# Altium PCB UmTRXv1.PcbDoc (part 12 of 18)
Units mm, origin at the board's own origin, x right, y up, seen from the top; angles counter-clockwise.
Board outline 172 x 113 mm, 6 copper layers (Top Layer, GND, MidLayer1, Mid-Layer 2, InternalPlane2, Bottom Layer); 766 components, 613 nets, 3008 pads, 1360 vias.
Unrouted connection lines stored in the file: 2.
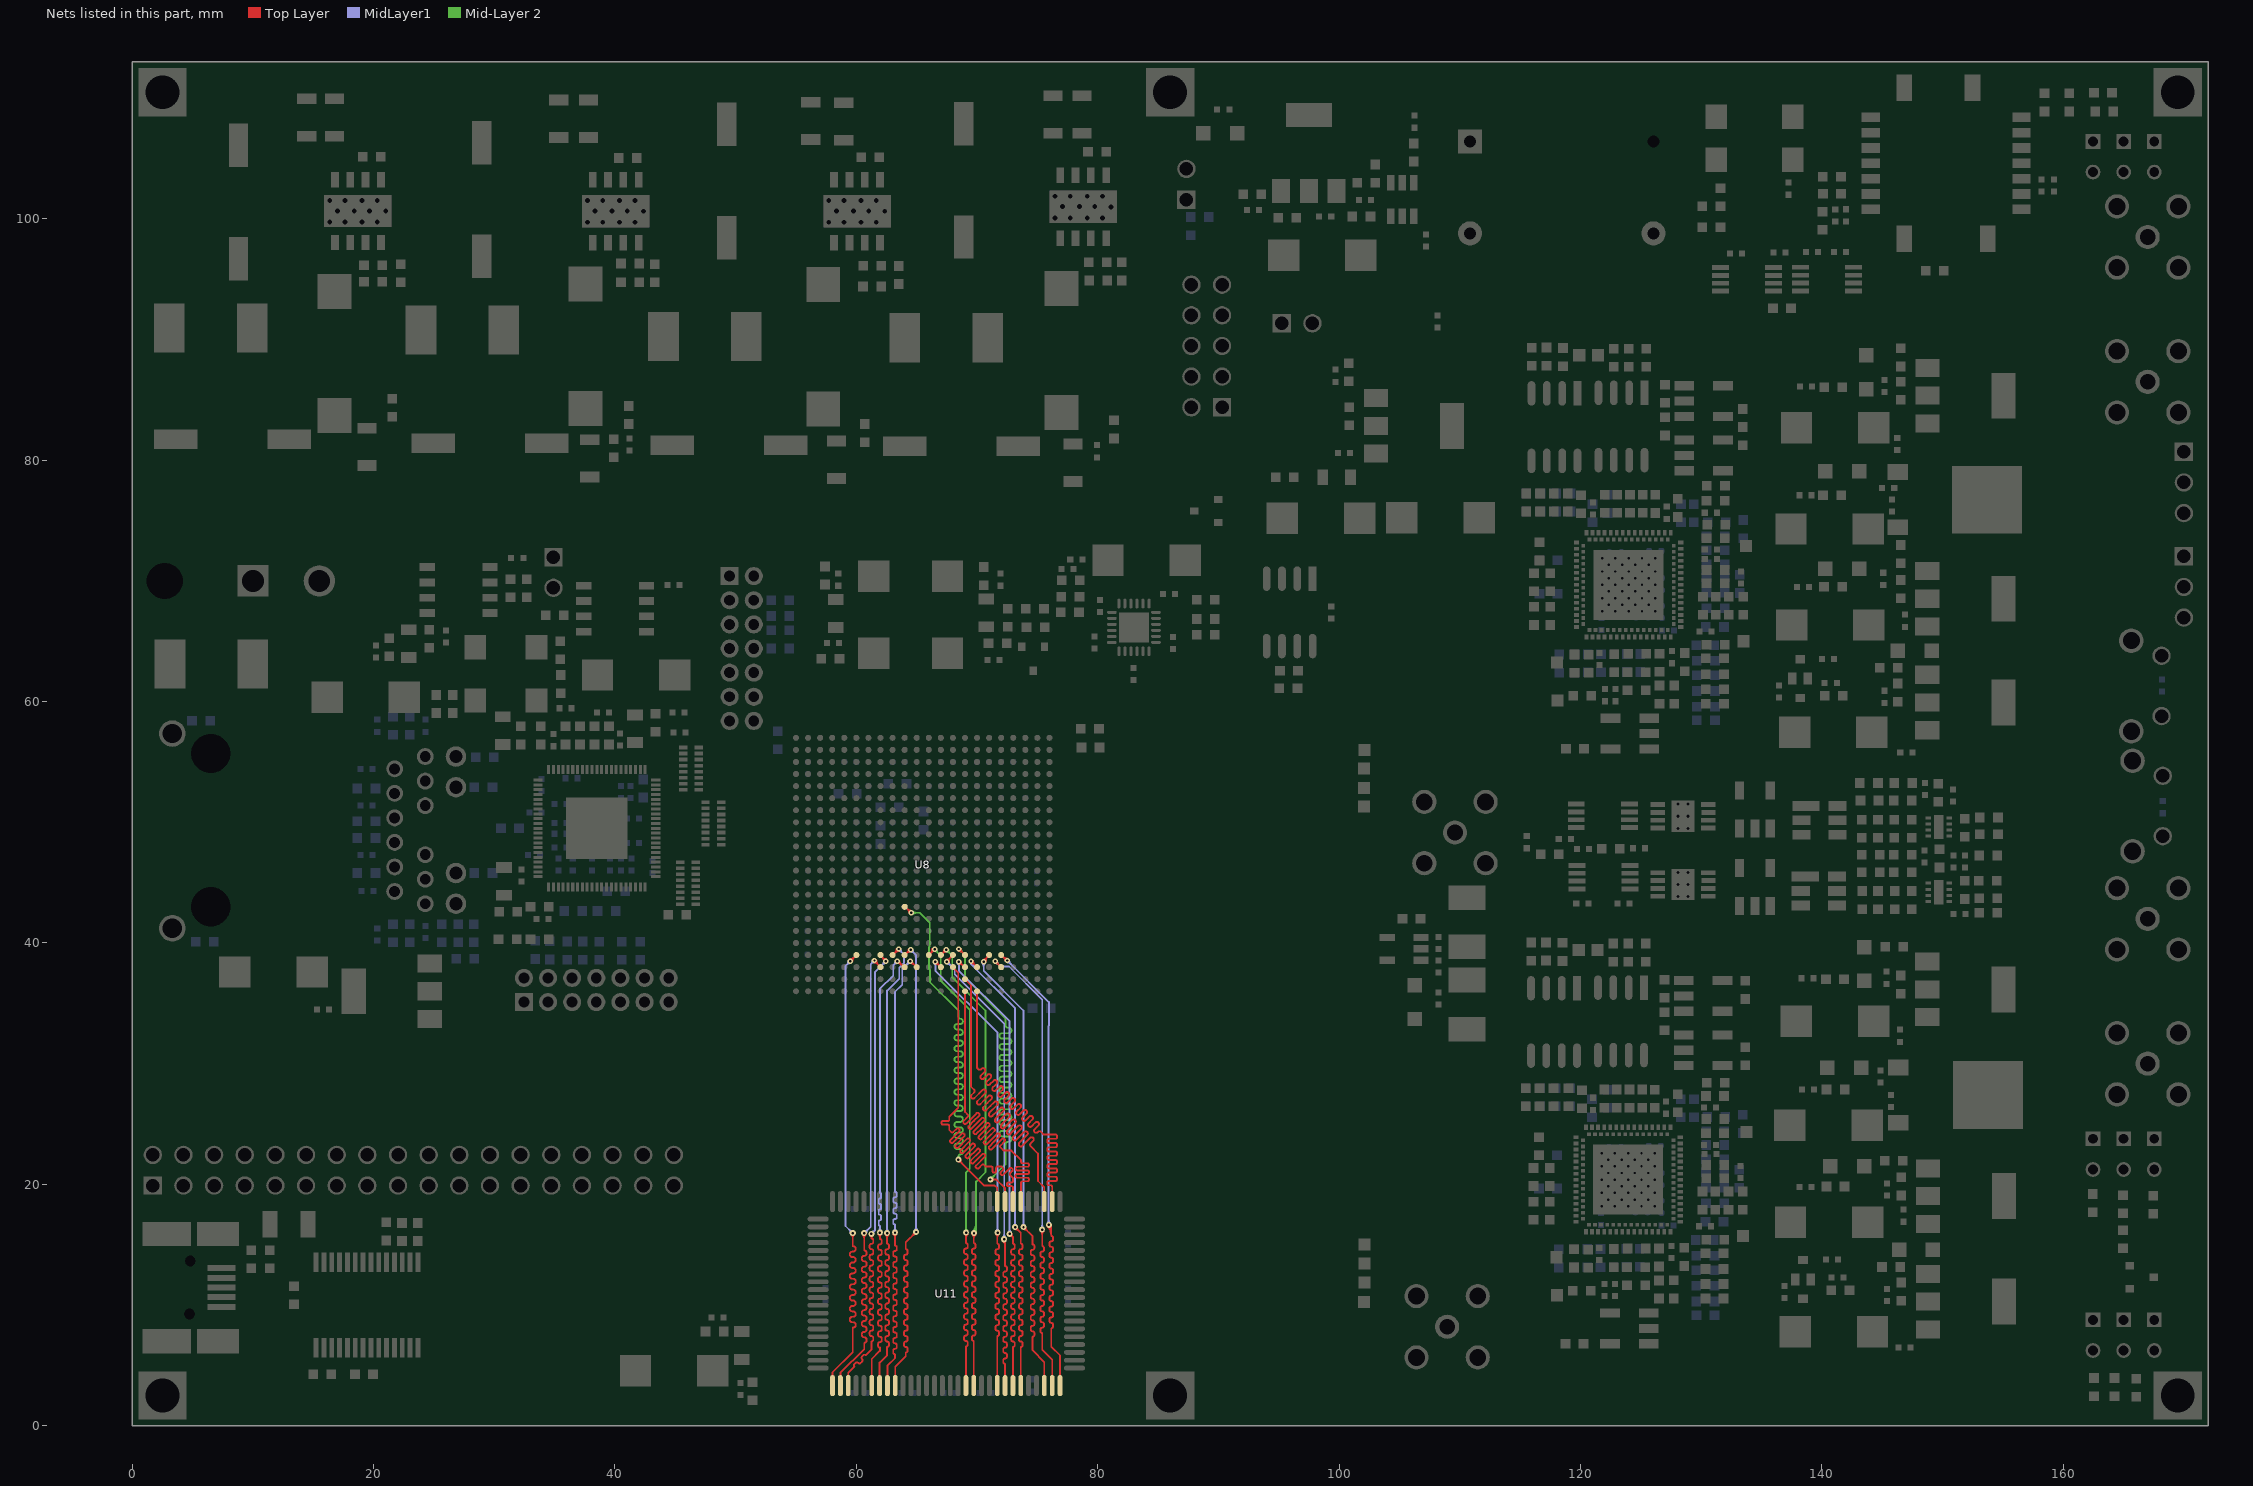
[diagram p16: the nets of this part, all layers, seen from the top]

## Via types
v1: diameter 0.45, hole 0.2, Top Layer to Bottom Layer, tented both sides, 554 vias
v2: diameter 0.5, hole 0.2, Top Layer to Bottom Layer, tented both sides, 468 vias
v3: diameter 0.7, hole 0.3, Top Layer to Bottom Layer, tented both sides, 206 vias
v4: diameter 0.4, hole 0.2, Top Layer to Bottom Layer, tented both sides, 82 vias
v5: diameter 0.8, hole 0.3, Top Layer to Bottom Layer, tented both sides, 16 vias
v6: diameter 0.6, hole 0.25, Top Layer to Bottom Layer, tented both sides, 16 vias
v7: diameter 0.5, hole 0.3, Top Layer to Bottom Layer, tented both sides, 8 vias
v8: diameter 0.7, hole 0.3, Top Layer to Bottom Layer, 4 vias
v9: diameter 0.6, hole 0.3, Top Layer to Bottom Layer, tented both sides, 4 vias
v10: diameter 0.5, hole 0.2, Top Layer to Bottom Layer, 2 vias

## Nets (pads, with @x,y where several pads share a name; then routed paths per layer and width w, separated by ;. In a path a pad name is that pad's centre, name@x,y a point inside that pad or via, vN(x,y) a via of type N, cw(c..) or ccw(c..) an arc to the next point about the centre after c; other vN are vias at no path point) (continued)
RAM_D02: U8.D13 U11.59 | length 43.8
  Top Layer w0.15: U11.59@63.225,3.325 63.225,4.875 64.1,5.75 64.1,6.075 ccw(c64.1,6.225) 64.25,6.225 64.25,6.375 ccw(c64.1,6.375) 64.1,6.525 cw(c64.1,6.675) 63.95,6.675 63.95,6.825 cw(c64.1,6.825) 64.1,6.975 ccw(c64.1,7.125) 64.25,7.125 64.25,7.275 ccw(c64.1,7.275) 64.1,7.425 cw(c64.1,7.575) 63.95,7.575 63.95,7.725 cw(c64.1,7.725) 64.1,7.875 ccw(c64.1,8.025) 64.25,8.025 64.25,8.175 ccw(c64.1,8.175) 64.1,8.325 cw(c64.1,8.475) 63.95,8.475 63.95,8.625 cw(c64.1,8.625) 64.1,8.775 ccw(c64.1,8.925) 64.25,8.925 64.25,9.075 ccw(c64.1,9.075) 64.1,9.225 cw(c64.1,9.375) 63.95,9.375 63.95,9.525 cw(c64.1,9.525) 64.1,9.675 ccw(c64.1,9.825) 64.25,9.825 64.25,9.975 ccw(c64.1,9.975) 64.1,10.125 cw(c64.1,10.275) 63.95,10.275 63.95,10.425 cw(c64.1,10.425) 64.1,10.575 ccw(c64.1,10.725) 64.25,10.725 64.25,10.875 ccw(c64.1,10.875) 64.1,11.025 cw(c64.1,11.175) 63.95,11.175 63.95,11.325 cw(c64.1,11.325) 64.1,11.475 ccw(c64.1,11.625) 64.25,11.625 64.25,11.775 ccw(c64.1,11.775) 64.1,11.925 cw(c64.1,12.075) 63.95,12.075 63.95,12.225 cw(c64.1,12.225) 64.1,12.375 ccw(c64.1,12.525) 64.25,12.525 64.25,12.675 ccw(c64.1,12.675) 64.1,12.825 cw(c64.1,12.975) 63.95,12.975 63.95,13.125 cw(c64.1,13.125) 64.1,13.275 ccw(c64.1,13.425) 64.25,13.425 64.25,13.575 ccw(c64.1,13.575) 64.1,13.725 cw(c64.1,13.875) 63.95,13.875 63.95,14.025 cw(c64.1,14.025) 64.1,14.175 ccw(c64.1,14.325) 64.25,14.325 64.25,14.475 ccw(c64.1,14.475) 64.1,14.625 64.1,15.2 v2(64.95,16.05) ; U8.D13@64,39 64.45,39.45 v1(64.5,39.45) v1@64.351,39.301 ; U8.D13@64.116,39.116 cw(c64.5,38.732) v1@64.5,39.275 ; 64.237,39.237 ccw(c64.023,39.45) v1@64.325,39.45 ; v2@64.775,16.05 cw(c64.353,16.05) 64.651,15.751 cw(c64.95,15.453) v2@64.95,15.875
  MidLayer1 w0.15: v1@64.5,39.275 cw(c64.5,38.853) 64.799,39.151 cw(c65.097,39.45) v1@64.675,39.45 ; v1(64.5,39.45) 64.95,39 v2(64.95,16.05) ; v2@64.826,16.174 ccw(c64.528,16.472) 64.95,16.472 ccw(c65.372,16.472) v2@65.074,16.174
RAM_D03: U8.C12 U11.58 | length 43.8
  Top Layer w0.15: U11.58@62.575,3.325 62.575,4.975 63.2,5.6 63.2,5.925 cw(c63.2,6.075) 63.05,6.075 63.05,6.225 cw(c63.2,6.225) 63.2,6.375 ccw(c63.2,6.525) 63.35,6.525 63.35,6.675 ccw(c63.2,6.675) 63.2,6.825 cw(c63.2,6.975) 63.05,6.975 63.05,7.125 cw(c63.2,7.125) 63.2,7.275 ccw(c63.2,7.425) 63.35,7.425 63.35,7.575 ccw(c63.2,7.575) 63.2,7.725 cw(c63.2,7.875) 63.05,7.875 63.05,8.025 cw(c63.2,8.025) 63.2,8.175 ccw(c63.2,8.325) 63.35,8.325 63.35,8.475 ccw(c63.2,8.475) 63.2,8.625 cw(c63.2,8.775) 63.05,8.775 63.05,8.925 cw(c63.2,8.925) 63.2,9.075 ccw(c63.2,9.225) 63.35,9.225 63.35,9.375 ccw(c63.2,9.375) 63.2,9.525 cw(c63.2,9.675) 63.05,9.675 63.05,9.825 cw(c63.2,9.825) 63.2,9.975 ccw(c63.2,10.125) 63.35,10.125 63.35,10.275 ccw(c63.2,10.275) 63.2,10.425 cw(c63.2,10.575) 63.05,10.575 63.05,10.725 cw(c63.2,10.725) 63.2,10.875 ccw(c63.2,11.025) 63.35,11.025 63.35,11.175 ccw(c63.2,11.175) 63.2,11.325 cw(c63.2,11.475) 63.05,11.475 63.05,11.625 cw(c63.2,11.625) 63.2,11.775 ccw(c63.2,11.925) 63.35,11.925 63.35,12.075 ccw(c63.2,12.075) 63.2,12.225 cw(c63.2,12.375) 63.05,12.375 63.05,12.525 cw(c63.2,12.525) 63.2,12.675 ccw(c63.2,12.825) 63.35,12.825 63.35,12.975 ccw(c63.2,12.975) 63.2,13.125 cw(c63.2,13.275) 63.05,13.275 63.05,13.425 cw(c63.2,13.425) 63.2,13.575 ccw(c63.2,13.725) 63.35,13.725 63.35,13.875 ccw(c63.2,13.875) 63.2,14.025 cw(c63.2,14.175) 63.05,14.175 63.05,14.325 cw(c63.2,14.325) 63.2,14.475 ccw(c63.2,14.625) 63.35,14.625 63.35,14.775 ccw(c63.2,14.775) 63.2,14.925 v2(63.2,16) ; v2@63.076,15.876 cw(c62.778,15.578) 63.2,15.578 cw(c63.622,15.578) v2@63.324,15.876 ; v1@64.45,38.325 cw(c64.45,37.782) U8.C12@64.834,38.166 ; v1(64.45,38.5) 64.5,38.5 U8.C12@65,38 ; v1@64.625,38.5 ccw(c64.927,38.5) 64.713,38.287
  MidLayer1 w0.15: v2@63.076,16.124 ccw(c62.778,16.422) 63.2,16.422 ccw(c63.622,16.422) v2@63.324,16.124 ; v2(63.2,16) 63.2,16.675 cw(c63.2,16.825) 63.05,16.825 63.05,16.975 cw(c63.2,16.975) 63.2,17.125 ccw(c63.2,17.275) 63.35,17.275 63.35,17.425 ccw(c63.2,17.425) 63.2,17.575 cw(c63.2,17.725) 63.05,17.725 63.05,17.875 cw(c63.2,17.875) 63.2,18.025 ccw(c63.2,18.175) 63.35,18.175 63.35,18.325 ccw(c63.2,18.325) 63.2,18.475 cw(c63.2,18.625) 63.05,18.625 63.05,18.775 cw(c63.2,18.775) 63.2,18.925 ccw(c63.2,19.075) 63.35,19.075 63.35,19.225 ccw(c63.2,19.225) 63.2,19.375 63.2,35.95 63.8,36.55 63.8,37.85 v1(64.45,38.5) ; v1@64.275,38.5 cw(c63.853,38.5) 64.151,38.201 cw(c64.45,37.903) v1@64.45,38.325
RAM_D04: U8.D14 U11.57 | length 43.8
  Top Layer w0.15: U11.57@61.925,3.325 61.925,5.225 62.55,5.85 62.55,6.525 ccw(c62.55,6.675) 62.7,6.675 62.7,6.825 ccw(c62.55,6.825) 62.55,6.975 cw(c62.55,7.125) 62.4,7.125 62.4,7.275 cw(c62.55,7.275) 62.55,7.425 ccw(c62.55,7.575) 62.7,7.575 62.7,7.725 ccw(c62.55,7.725) 62.55,7.875 cw(c62.55,8.025) 62.4,8.025 62.4,8.175 cw(c62.55,8.175) 62.55,8.325 ccw(c62.55,8.475) 62.7,8.475 62.7,8.625 ccw(c62.55,8.625) 62.55,8.775 cw(c62.55,8.925) 62.4,8.925 62.4,9.075 cw(c62.55,9.075) 62.55,9.225 ccw(c62.55,9.375) 62.7,9.375 62.7,9.525 ccw(c62.55,9.525) 62.55,9.675 cw(c62.55,9.825) 62.4,9.825 62.4,9.975 cw(c62.55,9.975) 62.55,10.125 ccw(c62.55,10.275) 62.7,10.275 62.7,10.425 ccw(c62.55,10.425) 62.55,10.575 cw(c62.55,10.725) 62.4,10.725 62.4,10.875 cw(c62.55,10.875) 62.55,11.025 ccw(c62.55,11.175) 62.7,11.175 62.7,11.325 ccw(c62.55,11.325) 62.55,11.475 cw(c62.55,11.625) 62.4,11.625 62.4,11.775 cw(c62.55,11.775) 62.55,11.925 ccw(c62.55,12.075) 62.7,12.075 62.7,12.225 ccw(c62.55,12.225) 62.55,12.375 cw(c62.55,12.525) 62.4,12.525 62.4,12.675 cw(c62.55,12.675) 62.55,12.825 ccw(c62.55,12.975) 62.7,12.975 62.7,13.125 ccw(c62.55,13.125) 62.55,13.275 cw(c62.55,13.425) 62.4,13.425 62.4,13.575 cw(c62.55,13.575) 62.55,13.725 ccw(c62.55,13.875) 62.7,13.875 62.7,14.025 ccw(c62.55,14.025) 62.55,14.175 cw(c62.55,14.325) 62.4,14.325 62.4,14.475 cw(c62.55,14.475) 62.55,14.625 ccw(c62.55,14.775) 62.7,14.775 62.7,14.925 ccw(c62.55,14.925) 62.55,15.075 v2(62.55,15.95) ; v2@62.426,15.826 cw(c62.128,15.528) 62.55,15.528 cw(c62.972,15.528) v2@62.674,15.826 ; U8.D14@63,39 v1(63.5,39.5) ; v1@63.325,39.5 cw(c62.903,39.5) 63.201,39.201 cw(c63.5,38.903) v1@63.5,39.325
  MidLayer1 w0.15: v2@62.426,16.074 ccw(c62.128,16.372) 62.55,16.372 ccw(c62.972,16.372) v2@62.674,16.074 ; v2(62.55,15.95) 62.55,36.05 63.55,37.05 63.55,37.954 63.95,38.354 63.95,39.05 v1(63.5,39.5) ; v1@63.5,39.325 cw(c63.5,38.903) 63.799,39.201 cw(c64.097,39.5) v1@63.675,39.5
RAM_D05: U8.C13 U11.56 | length 43.6
  Top Layer w0.15: U11.56@61.275,3.325 61.275,5.525 61.95,6.2 61.95,6.475 cw(c61.95,6.625) 61.8,6.625 61.8,6.775 cw(c61.95,6.775) 61.95,6.925 ccw(c61.95,7.075) 62.1,7.075 62.1,7.225 ccw(c61.95,7.225) 61.95,7.375 cw(c61.95,7.525) 61.8,7.525 61.8,7.675 cw(c61.95,7.675) 61.95,7.825 ccw(c61.95,7.975) 62.1,7.975 62.1,8.125 ccw(c61.95,8.125) 61.95,8.275 cw(c61.95,8.425) 61.8,8.425 61.8,8.575 cw(c61.95,8.575) 61.95,8.725 ccw(c61.95,8.875) 62.1,8.875 62.1,9.025 ccw(c61.95,9.025) 61.95,9.175 cw(c61.95,9.325) 61.8,9.325 61.8,9.475 cw(c61.95,9.475) 61.95,9.625 ccw(c61.95,9.775) 62.1,9.775 62.1,9.925 ccw(c61.95,9.925) 61.95,10.075 cw(c61.95,10.225) 61.8,10.225 61.8,10.375 cw(c61.95,10.375) 61.95,10.525 ccw(c61.95,10.675) 62.1,10.675 62.1,10.825 ccw(c61.95,10.825) 61.95,10.975 cw(c61.95,11.125) 61.8,11.125 61.8,11.275 cw(c61.95,11.275) 61.95,11.425 ccw(c61.95,11.575) 62.1,11.575 62.1,11.725 ccw(c61.95,11.725) 61.95,11.875 cw(c61.95,12.025) 61.8,12.025 61.8,12.175 cw(c61.95,12.175) 61.95,12.325 ccw(c61.95,12.475) 62.1,12.475 62.1,12.625 ccw(c61.95,12.625) 61.95,12.775 cw(c61.95,12.925) 61.8,12.925 61.8,13.075 cw(c61.95,13.075) 61.95,13.225 ccw(c61.95,13.375) 62.1,13.375 62.1,13.525 ccw(c61.95,13.525) 61.95,13.675 cw(c61.95,13.825) 61.8,13.825 61.8,13.975 cw(c61.95,13.975) 61.95,14.125 ccw(c61.95,14.275) 62.1,14.275 62.1,14.425 ccw(c61.95,14.425) 61.95,14.575 cw(c61.95,14.725) 61.8,14.725 61.8,14.875 cw(c61.95,14.875) 61.95,15.025 ccw(c61.95,15.175) 62.1,15.175 62.1,15.325 ccw(c61.95,15.325) 61.95,15.475 v2(61.95,16) ; v2@61.826,15.876 cw(c61.528,15.578) 61.95,15.578 cw(c62.372,15.578) v2@62.074,15.876 ; v1@63.4,38.325 cw(c63.4,37.782) 63.784,38.166 ; v1(63.4,38.5) 63.45,38.5 U8.C13@63.975,37.975 ; v1@63.575,38.5 ccw(c63.877,38.5) 63.663,38.287
  MidLayer1 w0.15: v2@61.826,16.124 ccw(c61.528,16.422) 61.95,16.422 ccw(c62.372,16.422) v2@62.074,16.124 ; v2(61.95,16) 61.95,16.575 cw(c61.95,16.675) 61.85,16.675 61.85,16.925 cw(c61.95,16.925) 61.95,17.025 ccw(c61.95,17.125) 62.05,17.125 62.05,17.375 ccw(c61.95,17.375) 61.95,17.475 cw(c61.95,17.575) 61.85,17.575 61.85,17.825 cw(c61.95,17.825) 61.95,17.925 ccw(c61.95,18.025) 62.05,18.025 62.05,18.275 ccw(c61.95,18.275) 61.95,18.375 cw(c61.95,18.475) 61.85,18.475 61.85,18.725 cw(c61.95,18.725) 61.95,18.825 ccw(c61.95,18.925) 62.05,18.925 62.05,19.175 ccw(c61.95,19.175) 61.95,19.275 61.95,36.2 63.05,37.3 63.05,38.15 v1(63.4,38.5) ; v1@63.225,38.5 cw(c62.803,38.5) 63.101,38.201 cw(c63.4,37.903) v1@63.4,38.325
RAM_D06: U8.D15 U11.53 | length 43.5
  Top Layer w0.15: U11.53@59.325,3.325 59.325,4.375 59.834,4.884 cw(c59.94,4.99) 59.834,5.096 ; 59.834,5.096 59.94,5.202 cw(c60.046,5.096) 60.152,5.202 ccw(c60.258,5.308) 60.364,5.202 ; 60.364,5.202 60.47,5.308 ccw(c60.364,5.414) 60.47,5.52 cw(c60.577,5.627) 60.47,5.732 ; 60.47,5.733 60.577,5.839 cw(c60.683,5.733) 60.789,5.839 61.25,6.3 61.25,6.975 ccw(c61.25,7.125) 61.4,7.125 61.4,7.275 ccw(c61.25,7.275) 61.25,7.425 cw(c61.25,7.575) 61.1,7.575 61.1,7.725 cw(c61.25,7.725) 61.25,7.875 ccw(c61.25,8.025) 61.4,8.025 61.4,8.175 ccw(c61.25,8.175) 61.25,8.325 cw(c61.25,8.475) 61.1,8.475 61.1,8.625 cw(c61.25,8.625) 61.25,8.775 ccw(c61.25,8.925) 61.4,8.925 61.4,9.075 ccw(c61.25,9.075) 61.25,9.225 cw(c61.25,9.375) 61.1,9.375 61.1,9.525 cw(c61.25,9.525) 61.25,9.675 ccw(c61.25,9.825) 61.4,9.825 61.4,9.975 ccw(c61.25,9.975) 61.25,10.125 cw(c61.25,10.275) 61.1,10.275 61.1,10.425 cw(c61.25,10.425) 61.25,10.575 ccw(c61.25,10.725) 61.4,10.725 61.4,10.875 ccw(c61.25,10.875) 61.25,11.025 cw(c61.25,11.175) 61.1,11.175 61.1,11.325 cw(c61.25,11.325) 61.25,11.475 ccw(c61.25,11.625) 61.4,11.625 61.4,11.775 ccw(c61.25,11.775) 61.25,11.925 cw(c61.25,12.075) 61.1,12.075 61.1,12.225 cw(c61.25,12.225) 61.25,12.375 ccw(c61.25,12.525) 61.4,12.525 61.4,12.675 ccw(c61.25,12.675) 61.25,12.825 cw(c61.25,12.975) 61.1,12.975 61.1,13.125 cw(c61.25,13.125) 61.25,13.275 ccw(c61.25,13.425) 61.4,13.425 61.4,13.575 ccw(c61.25,13.575) 61.25,13.725 cw(c61.25,13.875) 61.1,13.875 61.1,14.025 cw(c61.25,14.025) 61.25,14.175 ccw(c61.25,14.325) 61.4,14.325 61.4,14.475 ccw(c61.25,14.475) 61.25,14.625 cw(c61.25,14.775) 61.1,14.775 61.1,14.925 cw(c61.25,14.925) 61.25,15.075 ccw(c61.25,15.225) 61.4,15.225 61.4,15.375 ccw(c61.25,15.375) 61.25,15.525 ; v2@61.138,15.766 cw(c60.936,15.525) 61.25,15.525 ; v2(61.25,15.9) 61.25,15.525 ; v2@61.362,15.766 ccw(c61.564,15.525) 61.25,15.525 ; U8.D15@62,39 62,38.95 v1(62.45,38.5) ; v1@62.275,38.5 ccw(c61.853,38.5) 62.151,38.799 ccw(c62.45,39.097) v1@62.45,38.675
  MidLayer1 w0.15: v2(61.25,15.9) 61.55,16.201 61.55,37.6 v1(62.45,38.5) ; v2@61.25,16.075 ccw(c61.25,16.495) 61.547,16.198 ; v2@61.425,15.9 cw(c61.85,15.9) 61.549,16.201 ; v1@62.275,38.5 cw(c61.853,38.5) 62.151,38.201 cw(c62.45,37.903) v1@62.45,38.325
RAM_D07: U8.C15 U11.52 | length 43.7
  Top Layer w0.15: U11.52@58.675,3.325 58.675,4.375 60.65,6.35 60.65,6.875 ccw(c60.65,7.075) 60.85,7.075 60.85,7.125 ccw(c60.65,7.125) 60.65,7.325 cw(c60.65,7.525) 60.45,7.525 60.45,7.575 cw(c60.65,7.575) 60.65,7.775 ccw(c60.65,7.975) 60.85,7.975 60.85,8.025 ccw(c60.65,8.025) 60.65,8.225 cw(c60.65,8.425) 60.45,8.425 60.45,8.475 cw(c60.65,8.475) 60.65,8.675 ccw(c60.65,8.875) 60.85,8.875 60.85,8.925 ccw(c60.65,8.925) 60.65,9.125 cw(c60.65,9.325) 60.45,9.325 60.45,9.375 cw(c60.65,9.375) 60.65,9.575 ccw(c60.65,9.775) 60.85,9.775 60.85,9.825 ccw(c60.65,9.825) 60.65,10.025 cw(c60.65,10.225) 60.45,10.225 60.45,10.275 cw(c60.65,10.275) 60.65,10.475 ccw(c60.65,10.675) 60.85,10.675 60.85,10.725 ccw(c60.65,10.725) 60.65,10.925 cw(c60.65,11.125) 60.45,11.125 60.45,11.175 cw(c60.65,11.175) 60.65,11.375 ccw(c60.65,11.575) 60.85,11.575 60.85,11.625 ccw(c60.65,11.625) 60.65,11.825 cw(c60.65,12.025) 60.45,12.025 60.45,12.075 cw(c60.65,12.075) 60.65,12.275 ccw(c60.65,12.475) 60.85,12.475 60.85,12.525 ccw(c60.65,12.525) 60.65,12.725 cw(c60.65,12.925) 60.45,12.925 60.45,12.975 cw(c60.65,12.975) 60.65,13.175 ccw(c60.65,13.375) 60.85,13.375 60.85,13.425 ccw(c60.65,13.425) 60.65,13.625 cw(c60.65,13.825) 60.45,13.825 60.45,13.875 cw(c60.65,13.875) 60.65,14.075 ccw(c60.65,14.275) 60.85,14.275 60.85,14.325 ccw(c60.65,14.325) 60.65,14.525 v2(60.65,15.95) ; v2@60.526,15.826 cw(c60.228,15.528) 60.65,15.528 cw(c61.072,15.528) v2@60.774,15.826 ; v1@61.5,38.375 cw(c61.5,38.073) 61.713,38.287 ; v1(61.5,38.55) 61.5,38.5 U8.C15@62,38 ; v1@61.675,38.55 ccw(c62.218,38.55) U8.C15@61.834,38.166
  MidLayer1 w0.15: v2(60.65,15.95) 61.2,16.5 61.2,38.25 v1(61.5,38.55) ; v2@60.65,16.125 ccw(c60.65,16.547) 60.949,16.249 ccw(c61.247,15.95) v2@60.825,15.95 ; v1@61.325,38.55 cw(c60.903,38.55) 61.201,38.251 cw(c61.5,37.953) v1@61.5,38.375
RAM_D08: U8.D17 U11.51 | length 44.2
  Top Layer w0.15: U11.51@58.025,3.325 58.025,4.425 59.7,6.1 59.7,8.1 cw(c59.725,8.1) 59.725,8.125 ccw(c59.725,8.35) 59.95,8.35 ccw(c59.725,8.35) 59.725,8.575 59.675,8.575 cw(c59.675,8.8) 59.45,8.8 cw(c59.675,8.8) 59.675,9.025 59.725,9.025 ccw(c59.725,9.25) 59.95,9.25 ccw(c59.725,9.25) 59.725,9.475 59.675,9.475 cw(c59.675,9.7) 59.45,9.7 cw(c59.675,9.7) 59.675,9.925 59.725,9.925 ccw(c59.725,10.15) 59.95,10.15 ccw(c59.725,10.15) 59.725,10.375 59.675,10.375 cw(c59.675,10.6) 59.45,10.6 cw(c59.675,10.6) 59.675,10.825 59.725,10.825 ccw(c59.725,11.05) 59.95,11.05 ccw(c59.725,11.05) 59.725,11.275 59.675,11.275 cw(c59.675,11.5) 59.45,11.5 cw(c59.675,11.5) 59.675,11.725 59.725,11.725 ccw(c59.725,11.95) 59.95,11.95 ccw(c59.725,11.95) 59.725,12.175 59.675,12.175 cw(c59.675,12.4) 59.45,12.4 cw(c59.675,12.4) 59.675,12.625 59.725,12.625 ccw(c59.725,12.85) 59.95,12.85 ccw(c59.725,12.85) 59.725,13.075 59.675,13.075 cw(c59.675,13.3) 59.45,13.3 cw(c59.675,13.3) 59.675,13.525 59.725,13.525 ccw(c59.725,13.75) 59.95,13.75 ccw(c59.725,13.75) 59.725,13.975 59.675,13.975 cw(c59.675,14.2) 59.45,14.2 cw(c59.675,14.2) 59.675,14.425 59.725,14.425 ccw(c59.725,14.65) 59.95,14.65 ccw(c59.725,14.65) 59.725,14.875 cw(c59.725,14.9) 59.7,14.9 v2(59.7,15.95) ; v1(59.5,38.5) U8.D17@60,39 ; v1@59.5,38.675 ccw(c59.5,39.097) 59.799,38.799 ccw(c60.097,38.5) v1@59.675,38.5 ; v2@59.576,15.826 cw(c59.278,15.528) 59.7,15.528 cw(c60.122,15.528) v2@59.824,15.826
  MidLayer1 w0.15: v1@59.325,38.5 cw(c58.903,38.5) 59.201,38.201 cw(c59.5,37.903) v1@59.5,38.325 ; v1(59.5,38.5) 59.1,38.1 59.1,16.55 v2(59.7,15.95) ; v2@59.525,15.95 ccw(c59.103,15.95) 59.401,16.249 ccw(c59.7,16.547) v2@59.7,16.125
RAM_D09: U8.D11 U11.68 | length 44.5
  Top Layer w0.15: U8.D11@66,39 66.45,39.45 v1@66.45,39.5 ; U8.D11@66.116,39.116 ccw(c65.732,39.5) 66.275,39.5 ; 66.237,39.237 cw(c66.45,39.023) v1@66.45,39.325 ; 66.301,39.351 v1@66.45,39.5 ; v1@66.503,39.502 66.452,39.502 v1@66.45,39.5 ; v2@68.976,15.876 cw(c68.738,15.638) 69.075,15.638 ; U11.68@69.075,3.325 69.075,6.575 ccw(c69.075,6.725) 69.225,6.725 69.225,6.875 ccw(c69.075,6.875) 69.075,7.025 cw(c69.075,7.175) 68.925,7.175 68.925,7.325 cw(c69.075,7.325) 69.075,7.475 ccw(c69.075,7.625) 69.225,7.625 69.225,7.775 ccw(c69.075,7.775) 69.075,7.925 cw(c69.075,8.075) 68.925,8.075 68.925,8.225 cw(c69.075,8.225) 69.075,8.375 ccw(c69.075,8.525) 69.225,8.525 69.225,8.675 ccw(c69.075,8.675) 69.075,8.825 cw(c69.075,8.975) 68.925,8.975 68.925,9.125 cw(c69.075,9.125) 69.075,9.275 ccw(c69.075,9.425) 69.225,9.425 69.225,9.575 ccw(c69.075,9.575) 69.075,9.725 cw(c69.075,9.875) 68.925,9.875 68.925,10.025 cw(c69.075,10.025) 69.075,10.175 ccw(c69.075,10.325) 69.225,10.325 69.225,10.475 ccw(c69.075,10.475) 69.075,10.625 cw(c69.075,10.775) 68.925,10.775 68.925,10.925 cw(c69.075,10.925) 69.075,11.075 ccw(c69.075,11.225) 69.225,11.225 69.225,11.375 ccw(c69.075,11.375) 69.075,11.525 cw(c69.075,11.675) 68.925,11.675 68.925,11.825 cw(c69.075,11.825) 69.075,11.975 ccw(c69.075,12.125) 69.225,12.125 69.225,12.275 ccw(c69.075,12.275) 69.075,12.425 cw(c69.075,12.575) 68.925,12.575 68.925,12.725 cw(c69.075,12.725) 69.075,12.875 ccw(c69.075,13.025) 69.225,13.025 69.225,13.175 ccw(c69.075,13.175) 69.075,13.325 cw(c69.075,13.475) 68.925,13.475 68.925,13.625 cw(c69.075,13.625) 69.075,13.775 ccw(c69.075,13.925) 69.225,13.925 69.225,14.075 ccw(c69.075,14.075) 69.075,14.225 cw(c69.075,14.375) 68.925,14.375 68.925,14.525 cw(c69.075,14.525) 69.075,14.675 ccw(c69.075,14.825) 69.225,14.825 69.225,14.975 ccw(c69.075,14.975) 69.075,15.125 69.075,15.975 v2(69.1,16) ; 69.075,15.517 cw(c69.583,15.517) v2@69.224,15.876
  Mid-Layer 2 w0.15: v1@66.45,39.325 cw(c66.45,38.903) 66.749,39.201 cw(c67.047,39.5) v1@66.625,39.5 ; v1@66.503,39.502 66.452,39.502 66.45,39.5 67,38.95 67,36.875 69.4,34.475 69.4,21.3 69.075,20.975 69.075,16.025 v2(69.1,16) ; v2@68.976,16.124 ccw(c68.738,16.362) 69.075,16.362 ; 69.075,16.483 ccw(c69.583,16.483) v2@69.224,16.124
  other v1: 66.5,39.475
RAM_D10: U8.D10 U11.69 | length 44.9
  Top Layer w0.15: U8.D10@67,39 v1(67.45,39.45) ; v1@67.275,39.45 cw(c66.853,39.45) 67.151,39.151 cw(c67.45,38.853) v1@67.45,39.275 ; v2@69.626,15.826 cw(c69.388,15.588) 69.725,15.588 ; U11.69@69.725,3.325 69.725,7.025 cw(c69.725,7.175) 69.575,7.175 69.575,7.325 cw(c69.725,7.325) 69.725,7.475 ccw(c69.725,7.625) 69.875,7.625 69.875,7.775 ccw(c69.725,7.775) 69.725,7.925 cw(c69.725,8.075) 69.575,8.075 69.575,8.225 cw(c69.725,8.225) 69.725,8.375 ccw(c69.725,8.525) 69.875,8.525 69.875,8.675 ccw(c69.725,8.675) 69.725,8.825 cw(c69.725,8.975) 69.575,8.975 69.575,9.125 cw(c69.725,9.125) 69.725,9.275 ccw(c69.725,9.425) 69.875,9.425 69.875,9.575 ccw(c69.725,9.575) 69.725,9.725 cw(c69.725,9.875) 69.575,9.875 69.575,10.025 cw(c69.725,10.025) 69.725,10.175 ccw(c69.725,10.325) 69.875,10.325 69.875,10.475 ccw(c69.725,10.475) 69.725,10.625 cw(c69.725,10.775) 69.575,10.775 69.575,10.925 cw(c69.725,10.925) 69.725,11.075 ccw(c69.725,11.225) 69.875,11.225 69.875,11.375 ccw(c69.725,11.375) 69.725,11.525 cw(c69.725,11.675) 69.575,11.675 69.575,11.825 cw(c69.725,11.825) 69.725,11.975 ccw(c69.725,12.125) 69.875,12.125 69.875,12.275 ccw(c69.725,12.275) 69.725,12.425 cw(c69.725,12.575) 69.575,12.575 69.575,12.725 cw(c69.725,12.725) 69.725,12.875 ccw(c69.725,13.025) 69.875,13.025 69.875,13.175 ccw(c69.725,13.175) 69.725,13.325 cw(c69.725,13.475) 69.575,13.475 69.575,13.625 cw(c69.725,13.625) 69.725,13.775 ccw(c69.725,13.925) 69.875,13.925 69.875,14.075 ccw(c69.725,14.075) 69.725,14.225 cw(c69.725,14.375) 69.575,14.375 69.575,14.525 cw(c69.725,14.525) 69.725,14.675 ccw(c69.725,14.825) 69.875,14.825 69.875,14.975 ccw(c69.725,14.975) 69.725,15.125 69.725,15.925 v2(69.75,15.95) ; 69.725,15.467 cw(c70.233,15.467) v2@69.874,15.826
  Mid-Layer 2 w0.15: v1@67.45,39.275 cw(c67.45,38.853) 67.749,39.151 cw(c68.047,39.45) v1@67.625,39.45 ; v1(67.45,39.45) 67.95,38.95 67.95,37.15 70.7,34.4 70.7,21 69.925,20.225 69.925,16.125 v2(69.75,15.95) ; v2@69.626,16.074 ccw(c68.905,16.795) 69.925,16.795 ; v2@69.732,15.968 ccw(c69.267,16.433) 69.925,16.433
RAM_D11: U8.C10 U11.72 | length 43.5
  Top Layer w0.15: v1@66.55,38.275 cw(c66.55,37.853) 66.849,38.151 cw(c67.147,38.45) v1@66.725,38.45 ; v1@66.6,38.45 v1(66.55,38.45) U8.C10@67,38 ; v2@71.576,15.876 cw(c71.338,15.638) 71.675,15.638 ; U11.72@71.675,3.325 71.675,7.425 ccw(c71.675,7.575) 71.825,7.575 71.825,7.725 ccw(c71.675,7.725) 71.675,7.875 cw(c71.675,8.025) 71.525,8.025 71.525,8.175 cw(c71.675,8.175) 71.675,8.325 ccw(c71.675,8.475) 71.825,8.475 71.825,8.625 ccw(c71.675,8.625) 71.675,8.775 cw(c71.675,8.925) 71.525,8.925 71.525,9.075 cw(c71.675,9.075) 71.675,9.225 ccw(c71.675,9.375) 71.825,9.375 71.825,9.525 ccw(c71.675,9.525) 71.675,9.675 cw(c71.675,9.825) 71.525,9.825 71.525,9.975 cw(c71.675,9.975) 71.675,10.125 ccw(c71.675,10.275) 71.825,10.275 71.825,10.425 ccw(c71.675,10.425) 71.675,10.575 cw(c71.675,10.725) 71.525,10.725 71.525,10.875 cw(c71.675,10.875) 71.675,11.025 ccw(c71.675,11.175) 71.825,11.175 71.825,11.325 ccw(c71.675,11.325) 71.675,11.475 cw(c71.675,11.625) 71.525,11.625 71.525,11.775 cw(c71.675,11.775) 71.675,11.925 ccw(c71.675,12.075) 71.825,12.075 71.825,12.225 ccw(c71.675,12.225) 71.675,12.375 cw(c71.675,12.525) 71.525,12.525 71.525,12.675 cw(c71.675,12.675) 71.675,12.825 ccw(c71.675,12.975) 71.825,12.975 71.825,13.125 ccw(c71.675,13.125) 71.675,13.275 cw(c71.675,13.425) 71.525,13.425 71.525,13.575 cw(c71.675,13.575) 71.675,13.725 ccw(c71.675,13.875) 71.825,13.875 71.825,14.025 ccw(c71.675,14.025) 71.675,14.175 cw(c71.675,14.325) 71.525,14.325 71.525,14.475 cw(c71.675,14.475) 71.675,14.625 ccw(c71.675,14.775) 71.825,14.775 71.825,14.925 ccw(c71.675,14.925) 71.675,15.075 71.675,15.975 v2(71.7,16) ; 71.675,15.517 cw(c72.183,15.517) v2@71.824,15.876
  MidLayer1 w0.15: v1@66.426,38.326 cw(c66.128,38.028) 66.55,38.028 cw(c66.972,38.028) v1@66.674,38.326 ; v1(66.55,38.45) 66.55,37.7 71.7,32.55 v2(71.7,16) ; v2@71.576,16.124 ccw(c71.278,16.422) 71.7,16.422 ccw(c72.122,16.422) v2@71.824,16.124
RAM_D12: U8.D9 U11.73 | length 43.9
  Top Layer w0.15: v1(67.5,38.45) 67.5,38.5 U8.D9@68,39 ; v1@67.5,38.625 ccw(c67.5,38.927) 67.713,38.713 ; v1@67.675,38.45 cw(c68.218,38.45) U8.D9@67.834,38.834 ; v2@72.126,15.326 cw(c71.646,14.846) 72.325,14.846 ; v2@72.232,15.432 cw(c72.009,15.209) 72.325,15.209 cw(c72.491,15.209) v2@72.374,15.326 ; v2(72.25,15.45) 72.325,15.375 72.325,13.225 cw(c72.325,13.075) 72.475,13.075 72.475,12.925 cw(c72.325,12.925) 72.325,12.775 ccw(c72.325,12.625) 72.175,12.625 72.175,12.475 ccw(c72.325,12.475) 72.325,12.325 cw(c72.325,12.175) 72.475,12.175 72.475,12.025 cw(c72.325,12.025) 72.325,11.875 ccw(c72.325,11.725) 72.175,11.725 72.175,11.575 ccw(c72.325,11.575) 72.325,11.425 cw(c72.325,11.275) 72.475,11.275 72.475,11.125 cw(c72.325,11.125) 72.325,10.975 ccw(c72.325,10.825) 72.175,10.825 72.175,10.675 ccw(c72.325,10.675) 72.325,10.525 cw(c72.325,10.375) 72.475,10.375 72.475,10.225 cw(c72.325,10.225) 72.325,10.075 ccw(c72.325,9.925) 72.175,9.925 72.175,9.775 ccw(c72.325,9.775) 72.325,9.625 cw(c72.325,9.475) 72.475,9.475 72.475,9.325 cw(c72.325,9.325) 72.325,9.175 ccw(c72.325,9.025) 72.175,9.025 72.175,8.875 ccw(c72.325,8.875) 72.325,8.725 cw(c72.325,8.575) 72.475,8.575 72.475,8.425 cw(c72.325,8.425) 72.325,8.275 ccw(c72.325,8.125) 72.175,8.125 72.175,7.975 ccw(c72.325,7.975) 72.325,7.825 cw(c72.325,7.675) 72.475,7.675 72.475,7.525 cw(c72.325,7.525) 72.325,7.375 ccw(c72.325,7.225) 72.175,7.225 72.175,7.075 ccw(c72.325,7.075) 72.325,6.925 cw(c72.325,6.775) 72.475,6.775 72.475,6.625 cw(c72.325,6.625) 72.325,6.475 ccw(c72.325,6.325) 72.175,6.325 72.175,6.175 ccw(c72.325,6.175) 72.325,6.025 cw(c72.325,5.875) 72.475,5.875 72.475,5.725 cw(c72.325,5.725) 72.325,5.575 ccw(c72.325,5.425) 72.175,5.425 72.175,5.275 ccw(c72.325,5.275) 72.325,5.125 U11.73@72.325,3.325
  MidLayer1 w0.15: v1@67.5,38.275 cw(c67.5,37.853) 67.799,38.151 cw(c68.097,38.45) v1@67.675,38.45 ; v1(67.5,38.45) 68.15,37.8 68.15,37.4 72.25,33.3 v2(72.25,15.45) ; v2@72.126,15.574 ccw(c71.828,15.872) 72.25,15.872 ccw(c72.672,15.872) v2@72.374,15.574
RAM_D13: U8.C8 U11.74 | length 43.5
  Top Layer w0.15: v1@68.5,38.275 cw(c68.5,37.853) 68.799,38.151 cw(c69.097,38.45) v1@68.675,38.45 ; v1(68.5,38.45) U8.C8@68.975,37.975 ; v2(72.7,15.9) 72.975,15.625 ; v2@72.711,15.725 cw(c72.731,15.381) 72.975,15.625 ; v2@72.875,15.889 ccw(c73.219,15.869) 72.975,15.625 ; U11.74@72.975,3.325 72.975,6.525 ccw(c72.975,6.675) 73.125,6.675 73.125,6.825 ccw(c72.975,6.825) 72.975,6.975 cw(c72.975,7.125) 72.825,7.125 72.825,7.275 cw(c72.975,7.275) 72.975,7.425 ccw(c72.975,7.575) 73.125,7.575 73.125,7.725 ccw(c72.975,7.725) 72.975,7.875 cw(c72.975,8.025) 72.825,8.025 72.825,8.175 cw(c72.975,8.175) 72.975,8.325 ccw(c72.975,8.475) 73.125,8.475 73.125,8.625 ccw(c72.975,8.625) 72.975,8.775 cw(c72.975,8.925) 72.825,8.925 72.825,9.075 cw(c72.975,9.075) 72.975,9.225 ccw(c72.975,9.375) 73.125,9.375 73.125,9.525 ccw(c72.975,9.525) 72.975,9.675 cw(c72.975,9.825) 72.825,9.825 72.825,9.975 cw(c72.975,9.975) 72.975,10.125 ccw(c72.975,10.275) 73.125,10.275 73.125,10.425 ccw(c72.975,10.425) 72.975,10.575 cw(c72.975,10.725) 72.825,10.725 72.825,10.875 cw(c72.975,10.875) 72.975,11.025 ccw(c72.975,11.175) 73.125,11.175 73.125,11.325 ccw(c72.975,11.325) 72.975,11.475 cw(c72.975,11.625) 72.825,11.625 72.825,11.775 cw(c72.975,11.775) 72.975,11.925 ccw(c72.975,12.075) 73.125,12.075 73.125,12.225 ccw(c72.975,12.225) 72.975,12.375 cw(c72.975,12.525) 72.825,12.525 72.825,12.675 cw(c72.975,12.675) 72.975,12.825 ccw(c72.975,12.975) 73.125,12.975 73.125,13.125 ccw(c72.975,13.125) 72.975,13.275 cw(c72.975,13.425) 72.825,13.425 72.825,13.575 cw(c72.975,13.575) 72.975,13.725 ccw(c72.975,13.875) 73.125,13.875 73.125,14.025 ccw(c72.975,14.025) 72.975,14.175 cw(c72.975,14.325) 72.825,14.325 72.825,14.475 cw(c72.975,14.475) 72.975,14.625 ccw(c72.975,14.775) 73.125,14.775 73.125,14.925 ccw(c72.975,14.925) 72.975,15.075 72.975,15.625
  MidLayer1 w0.15: v1@68.376,38.326 cw(c68.078,38.028) 68.5,38.028 cw(c68.922,38.028) v1@68.624,38.326 ; v1(68.5,38.45) 68.5,37.7 72.7,33.5 v2(72.7,15.9) ; v2@72.576,16.024 ccw(c72.278,16.322) 72.7,16.322 ccw(c73.122,16.322) v2@72.824,16.024
RAM_D14: U8.C7 U11.75 | length 44.2
  Top Layer w0.15: v1@69.5,38.325 cw(c69.5,37.903) 69.799,38.201 cw(c70.097,38.5) v1@69.675,38.5 ; v1@69.55,38.5 v1(69.5,38.5) U8.C7@70,38 ; v2@73.15,16.275 cw(c73.15,15.853) 73.449,16.151 cw(c73.747,16.45) v2@73.325,16.45 ; v2(73.15,16.45) 73.625,15.975 73.625,15.075 cw(c73.625,14.925) 73.775,14.925 73.775,14.775 cw(c73.625,14.775) 73.625,14.625 ccw(c73.625,14.475) 73.475,14.475 73.475,14.325 ccw(c73.625,14.325) 73.625,14.175 cw(c73.625,14.025) 73.775,14.025 73.775,13.875 cw(c73.625,13.875) 73.625,13.725 ccw(c73.625,13.575) 73.475,13.575 73.475,13.425 ccw(c73.625,13.425) 73.625,13.275 cw(c73.625,13.125) 73.775,13.125 73.775,12.975 cw(c73.625,12.975) 73.625,12.825 ccw(c73.625,12.675) 73.475,12.675 73.475,12.525 ccw(c73.625,12.525) 73.625,12.375 cw(c73.625,12.225) 73.775,12.225 73.775,12.075 cw(c73.625,12.075) 73.625,11.925 ccw(c73.625,11.775) 73.475,11.775 73.475,11.625 ccw(c73.625,11.625) 73.625,11.475 cw(c73.625,11.325) 73.775,11.325 73.775,11.175 cw(c73.625,11.175) 73.625,11.025 ccw(c73.625,10.875) 73.475,10.875 73.475,10.725 ccw(c73.625,10.725) 73.625,10.575 cw(c73.625,10.425) 73.775,10.425 73.775,10.275 cw(c73.625,10.275) 73.625,10.125 ccw(c73.625,9.975) 73.475,9.975 73.475,9.825 ccw(c73.625,9.825) 73.625,9.675 cw(c73.625,9.525) 73.775,9.525 73.775,9.375 cw(c73.625,9.375) 73.625,9.225 ccw(c73.625,9.075) 73.475,9.075 73.475,8.925 ccw(c73.625,8.925) 73.625,8.775 cw(c73.625,8.625) 73.775,8.625 73.775,8.475 cw(c73.625,8.475) 73.625,8.325 ccw(c73.625,8.175) 73.475,8.175 73.475,8.025 ccw(c73.625,8.025) 73.625,7.875 cw(c73.625,7.725) 73.775,7.725 73.775,7.575 cw(c73.625,7.575) 73.625,7.425 ccw(c73.625,7.275) 73.475,7.275 73.475,7.125 ccw(c73.625,7.125) 73.625,6.975 cw(c73.625,6.825) 73.775,6.825 73.775,6.675 cw(c73.625,6.675) 73.625,6.525 U11.75@73.625,3.325
  MidLayer1 w0.15: v1(69.5,38.5) 69.5,38.25 73.15,34.6 v2(73.15,16.45) ; v1@69.525,38.5 ccw(c70.189,38.5) 69.719,38.031 ; v1@69.675,38.5 ccw(c70.701,38.5) 69.976,37.774 ; v2@73.026,16.574 ccw(c72.728,16.872) 73.15,16.872 ccw(c73.572,16.872) v2@73.274,16.574
RAM_D15: U8.D6 U11.78 | length 43.5
  Top Layer w0.15: v1(70.55,38.45) 70.55,38.55 U8.D6@71,39 ; v1@70.55,38.625 ccw(c70.55,38.806) 70.678,38.678 ; v1@70.725,38.45 cw(c71.389,38.45) U8.D6@70.919,38.919 ; v2@73.85,16.275 cw(c73.85,15.853) 74.149,16.151 cw(c74.447,16.45) v2@74.025,16.45 ; v2(73.85,16.45) 74.6,15.7 74.6,15.025 cw(c74.6,14.875) 74.75,14.875 74.75,14.725 cw(c74.6,14.725) 74.6,14.575 ccw(c74.6,14.425) 74.45,14.425 74.45,14.275 ccw(c74.6,14.275) 74.6,14.125 cw(c74.6,13.975) 74.75,13.975 74.75,13.825 cw(c74.6,13.825) 74.6,13.675 ccw(c74.6,13.525) 74.45,13.525 74.45,13.375 ccw(c74.6,13.375) 74.6,13.225 cw(c74.6,13.075) 74.75,13.075 74.75,12.925 cw(c74.6,12.925) 74.6,12.775 ccw(c74.6,12.625) 74.45,12.625 74.45,12.475 ccw(c74.6,12.475) 74.6,12.325 cw(c74.6,12.175) 74.75,12.175 74.75,12.025 cw(c74.6,12.025) 74.6,11.875 ccw(c74.6,11.725) 74.45,11.725 74.45,11.575 ccw(c74.6,11.575) 74.6,11.425 cw(c74.6,11.275) 74.75,11.275 74.75,11.125 cw(c74.6,11.125) 74.6,10.975 ccw(c74.6,10.825) 74.45,10.825 74.45,10.675 ccw(c74.6,10.675) 74.6,10.525 cw(c74.6,10.375) 74.75,10.375 74.75,10.225 cw(c74.6,10.225) 74.6,10.075 ccw(c74.6,9.925) 74.45,9.925 74.45,9.775 ccw(c74.6,9.775) 74.6,9.625 cw(c74.6,9.475) 74.75,9.475 74.75,9.325 cw(c74.6,9.325) 74.6,9.175 ccw(c74.6,9.025) 74.45,9.025 74.45,8.875 ccw(c74.6,8.875) 74.6,8.725 cw(c74.6,8.575) 74.75,8.575 74.75,8.425 cw(c74.6,8.425) 74.6,8.275 ccw(c74.6,8.125) 74.45,8.125 74.45,7.975 ccw(c74.6,7.975) 74.6,7.825 cw(c74.6,7.675) 74.75,7.675 74.75,7.525 cw(c74.6,7.525) 74.6,7.375 74.6,6.25 75.575,5.275 U11.78@75.575,3.325
  MidLayer1 w0.15: v1@70.426,38.326 cw(c70.128,38.028) 70.55,38.028 cw(c70.972,38.028) v1@70.674,38.326 ; v1(70.55,38.45) 70.55,37.7 73.85,34.4 v2(73.85,16.45) ; v2@73.726,16.574 ccw(c73.428,16.872) 73.85,16.872 ccw(c74.272,16.872) v2@73.974,16.574
RAM_D16: U8.C5 U11.79 | length 43.6
  Top Layer w0.15: v1@71.5,38.325 cw(c71.5,37.903) 71.799,38.201 cw(c72.097,38.5) v1@71.675,38.5 ; v1(71.5,38.5) U8.C5@72,38 ; v2@75.276,16.126 cw(c74.978,15.828) 75.4,15.828 cw(c75.822,15.828) v2@75.524,16.126 ; v2(75.4,16.25) 75.4,14.875 cw(c75.4,14.725) 75.55,14.725 75.55,14.575 cw(c75.4,14.575) 75.4,14.425 ccw(c75.4,14.275) 75.25,14.275 75.25,14.125 ccw(c75.4,14.125) 75.4,13.975 cw(c75.4,13.825) 75.55,13.825 75.55,13.675 cw(c75.4,13.675) 75.4,13.525 ccw(c75.4,13.375) 75.25,13.375 75.25,13.225 ccw(c75.4,13.225) 75.4,13.075 cw(c75.4,12.925) 75.55,12.925 75.55,12.775 cw(c75.4,12.775) 75.4,12.625 ccw(c75.4,12.475) 75.25,12.475 75.25,12.325 ccw(c75.4,12.325) 75.4,12.175 cw(c75.4,12.025) 75.55,12.025 75.55,11.875 cw(c75.4,11.875) 75.4,11.725 ccw(c75.4,11.575) 75.25,11.575 75.25,11.425 ccw(c75.4,11.425) 75.4,11.275 cw(c75.4,11.125) 75.55,11.125 75.55,10.975 cw(c75.4,10.975) 75.4,10.825 ccw(c75.4,10.675) 75.25,10.675 75.25,10.525 ccw(c75.4,10.525) 75.4,10.375 cw(c75.4,10.225) 75.55,10.225 75.55,10.075 cw(c75.4,10.075) 75.4,9.925 ccw(c75.4,9.775) 75.25,9.775 75.25,9.625 ccw(c75.4,9.625) 75.4,9.475 cw(c75.4,9.325) 75.55,9.325 75.55,9.175 cw(c75.4,9.175) 75.4,9.025 ccw(c75.4,8.875) 75.25,8.875 75.25,8.725 ccw(c75.4,8.725) 75.4,8.575 cw(c75.4,8.425) 75.55,8.425 75.55,8.275 cw(c75.4,8.275) 75.4,8.125 ccw(c75.4,7.975) 75.25,7.975 75.25,7.825 ccw(c75.4,7.825) 75.4,7.675 75.4,6.3 76.225,5.475 U11.79@76.225,3.325
  MidLayer1 w0.15: v1@71.5,38.325 cw(c71.5,37.903) 71.799,38.201 cw(c72.097,38.5) v1@71.675,38.5 ; v1(71.5,38.5) 71.95,38.05 72.65,38.05 75.4,35.3 v2(75.4,16.25) ; v2@75.276,16.374 ccw(c74.978,16.672) 75.4,16.672 ccw(c75.822,16.672) v2@75.524,16.374
RAM_D17: U8.D5 U11.80 | length 44.9
  Top Layer w0.15: U8.D5@72,39 72.45,38.55 v1(72.5,38.55) ; U8.D5@72.116,38.884 ccw(c72.5,39.268) v1@72.5,38.725 ; 72.237,38.763 cw(c72.023,38.55) v1@72.325,38.55 ; v2@75.826,16.526 cw(c75.045,15.745) 76.15,15.745 ; v2@75.932,16.632 cw(c75.407,16.107) 76.15,16.107 ; v2(75.95,16.65) 76.15,16.45 ; v2@76.006,16.484 cw(c76.05,16.35) 76.15,16.45 ; v2@76.038,16.738 cw(c75.769,16.469) 76.15,16.469 ; v2@76.116,16.594 ccw(c76.25,16.55) 76.15,16.45 ; U11.80@76.875,3.325 76.875,5.825 76.15,6.55 76.15,8.075 ccw(c76.15,8.225) 76.3,8.225 76.3,8.375 ccw(c76.15,8.375) 76.15,8.525 cw(c76.15,8.675) 76,8.675 76,8.825 cw(c76.15,8.825) 76.15,8.975 ccw(c76.15,9.125) 76.3,9.125 76.3,9.275 ccw(c76.15,9.275) 76.15,9.425 cw(c76.15,9.575) 76,9.575 76,9.725 cw(c76.15,9.725) 76.15,9.875 ccw(c76.15,10.025) 76.3,10.025 76.3,10.175 ccw(c76.15,10.175) 76.15,10.325 cw(c76.15,10.475) 76,10.475 76,10.625 cw(c76.15,10.625) 76.15,10.775 ccw(c76.15,10.925) 76.3,10.925 76.3,11.075 ccw(c76.15,11.075) 76.15,11.225 cw(c76.15,11.375) 76,11.375 76,11.525 cw(c76.15,11.525) 76.15,11.675 ccw(c76.15,11.825) 76.3,11.825 76.3,11.975 ccw(c76.15,11.975) 76.15,12.125 cw(c76.15,12.275) 76,12.275 76,12.425 cw(c76.15,12.425) 76.15,12.575 ccw(c76.15,12.725) 76.3,12.725 76.3,12.875 ccw(c76.15,12.875) 76.15,13.025 cw(c76.15,13.175) 76,13.175 76,13.325 cw(c76.15,13.325) 76.15,13.475 ccw(c76.15,13.625) 76.3,13.625 76.3,13.775 ccw(c76.15,13.775) 76.15,13.925 cw(c76.15,14.075) 76,14.075 76,14.225 cw(c76.15,14.225) 76.15,14.375 ccw(c76.15,14.525) 76.3,14.525 76.3,14.675 ccw(c76.15,14.675) 76.15,14.825 cw(c76.15,14.975) 76,14.975 76,15.125 cw(c76.15,15.125) 76.15,15.275 ccw(c76.15,15.425) 76.3,15.425 76.3,15.575 ccw(c76.15,15.575) 76.15,15.725 76.15,16.45
  MidLayer1 w0.15: v1@72.35,38.7 v1(72.5,38.55) 72.504,38.55 75.95,35.104 75.95,33.151 75.925,33.126 75.925,16.675 v2(75.95,16.65) ; v1@72.5,38.375 cw(c72.5,37.944) 72.805,38.249 ; v1@72.675,38.55 ccw(c73.089,38.55) 72.796,38.257 ; v2@75.826,16.774 ccw(c75.588,17.012) 75.925,17.012 ; 75.925,17.133 ccw(c76.433,17.133) v2@76.074,16.774
RAM_D18: U8.A7 U11.2 | length 41.3
  Top Layer w0.15: U8.A7@70,36 70,29.65 70.103,29.547 ccw(c70.227,29.671) 70.35,29.547 70.381,29.578 cw(c70.505,29.455) 70.629,29.578 cw(c70.505,29.455) 70.629,29.331 70.474,29.176 70.319,29.021 ccw(c70.443,28.897) 70.319,28.774 ccw(c70.443,28.897) 70.567,28.774 70.721,28.929 70.876,29.083 cw(c71,28.96) 71.124,29.083 cw(c71,28.96) 71.124,28.836 70.969,28.681 70.814,28.526 ccw(c70.938,28.403) 70.814,28.279 ccw(c70.938,28.403) 71.062,28.279 71.371,28.588 cw(c71.495,28.465) 71.619,28.588 cw(c71.495,28.465) 71.619,28.341 71.464,28.186 71.309,28.031 ccw(c71.433,27.908) 71.309,27.784 ccw(c71.433,27.908) 71.557,27.784 71.711,27.939 71.866,28.093 cw(c71.99,27.97) 72.114,28.093 cw(c71.99,27.97) 72.114,27.846 71.959,27.691 71.804,27.536 ccw(c71.928,27.413) 71.804,27.289 ccw(c71.928,27.413) 72.052,27.289 72.361,27.598 cw(c72.485,27.475) 72.609,27.598 cw(c72.485,27.475) 72.609,27.351 72.299,27.041 ccw(c72.423,26.918) 72.299,26.794 ccw(c72.423,26.918) 72.547,26.794 72.701,26.949 72.856,27.103 cw(c72.98,26.98) 73.104,27.103 cw(c72.98,26.98) 73.104,26.856 72.949,26.701 72.794,26.546 ccw(c72.918,26.423) 72.794,26.299 ccw(c72.918,26.423) 73.042,26.299 73.196,26.454 73.351,26.608 cw(c73.475,26.485) 73.599,26.608 cw(c73.475,26.485) 73.599,26.361 73.289,26.051 ccw(c73.413,25.928) 73.289,25.804 ccw(c73.413,25.928) 73.537,25.804 73.691,25.959 73.846,26.113 cw(c73.97,25.99) 74.094,26.113 cw(c73.97,25.99) 74.094,25.866 73.939,25.711 73.784,25.556 ccw(c73.908,25.433) 73.784,25.309 ccw(c73.908,25.433) 74.032,25.309 74.186,25.464 74.341,25.618 cw(c74.465,25.495) 74.589,25.618 cw(c74.465,25.495) 74.589,25.371 74.279,25.061 ccw(c74.403,24.938) 74.279,24.814 ccw(c74.403,24.938) 74.527,24.814 74.836,25.123 cw(c74.96,25) 75.084,25.123 cw(c74.96,25) 75.084,24.876 74.929,24.721 74.774,24.566 ccw(c74.898,24.443) 74.774,24.319 ccw(c74.898,24.443) 75.021,24.319 75.053,24.35 cw(c75.176,24.226) 75.3,24.35 75.525,24.125 76.503,24.125 cw(c76.503,24.002) 76.625,24.002 76.625,23.897 cw(c76.503,23.897) 76.503,23.775 75.947,23.775 ccw(c75.947,23.652) 75.825,23.652 75.825,23.547 ccw(c75.947,23.547) 75.947,23.425 76.503,23.425 cw(c76.503,23.302) 76.625,23.302 76.625,23.197 cw(c76.503,23.197) 76.503,23.075 75.947,23.075 ccw(c75.947,22.952) 75.825,22.952 75.825,22.847 ccw(c75.947,22.847) 75.947,22.725 76.503,22.725 cw(c76.503,22.602) 76.625,22.602 76.625,22.497 cw(c76.503,22.497) 76.503,22.375 75.947,22.375 ccw(c75.947,22.252) 75.825,22.252 75.825,22.147 ccw(c75.947,22.147) 75.947,22.025 76.503,22.025 cw(c76.503,21.902) 76.625,21.902 76.625,21.797 cw(c76.503,21.797) 76.503,21.675 75.947,21.675 ccw(c75.947,21.552) 75.825,21.552 75.825,21.447 ccw(c75.947,21.447) 75.947,21.325 76.503,21.325 cw(c76.503,21.202) 76.625,21.202 76.625,21.097 cw(c76.503,21.097) 76.503,20.975 75.947,20.975 ccw(c75.947,20.852) 75.825,20.852 75.825,20.747 ccw(c75.947,20.747) 75.947,20.625 76.503,20.625 cw(c76.503,20.502) 76.625,20.502 76.625,20.397 cw(c76.503,20.397) 76.503,20.275 75.947,20.275 ccw(c75.947,20.152) 75.825,20.152 75.825,20.047 ccw(c75.947,20.047) 75.947,19.925 76.102,19.925 cw(c76.102,19.803) 76.225,19.803 U11.2@76.225,18.575
RAM_D19: U8.B8 U11.3 | length 41.3
  Top Layer w0.15: U8.B8@69,37 69.5,36.5 69.5,28.1 69.747,27.853 cw(c69.624,27.729) 69.747,27.605 69.543,27.401 ccw(c69.667,27.277) 69.543,27.153 ccw(c69.667,27.277) 69.791,27.153 70.447,27.809 cw(c70.571,27.686) 70.694,27.809 cw(c70.571,27.686) 70.694,27.562 70.038,26.906 ccw(c70.162,26.782) 70.038,26.658 ccw(c70.162,26.782) 70.286,26.658 70.614,26.986 70.942,27.314 cw(c71.066,27.191) 71.189,27.314 cw(c71.066,27.191) 71.189,27.067 70.861,26.739 70.533,26.411 ccw(c70.657,26.287) 70.533,26.163 ccw(c70.657,26.287) 70.781,26.163 71.109,26.491 71.437,26.819 cw(c71.561,26.696) 71.684,26.819 cw(c71.561,26.696) 71.684,26.572 71.028,25.916 ccw(c71.152,25.792) 71.028,25.668 ccw(c71.152,25.792) 71.276,25.668 71.604,25.996 71.932,26.324 cw(c72.056,26.201) 72.179,26.324 cw(c72.056,26.201) 72.179,26.077 71.851,25.749 71.523,25.421 ccw(c71.647,25.297) 71.523,25.173 ccw(c71.647,25.297) 71.77,25.173 72.099,25.501 72.427,25.83 cw(c72.55,25.706) 72.674,25.83 cw(c72.55,25.706) 72.674,25.582 72.018,24.926 ccw(c72.142,24.802) 72.018,24.678 ccw(c72.142,24.802) 72.265,24.678 72.922,25.335 cw(c73.045,25.211) 73.169,25.335 cw(c73.045,25.211) 73.169,25.087 72.841,24.759 72.513,24.431 ccw(c72.637,24.307) 72.513,24.183 ccw(c72.637,24.307) 72.76,24.183 73.089,24.511 73.417,24.84 cw(c73.54,24.716) 73.664,24.84 cw(c73.54,24.716) 73.664,24.592 73.336,24.264 73.008,23.936 ccw(c73.132,23.812) 73.008,23.688 ccw(c73.132,23.812) 73.255,23.688 73.912,24.345 cw(c74.035,24.221) 74.159,24.345 cw(c74.035,24.221) 74.159,24.097 73.831,23.769 73.503,23.441 ccw(c73.627,23.317) 73.503,23.193 ccw(c73.627,23.317) 73.75,23.193 74.079,23.521 74.407,23.85 cw(c74.53,23.726) 74.654,23.85 cw(c74.53,23.726) 74.654,23.602 74.45,23.398 ccw(c74.573,23.274) 74.45,23.15 75.05,22.55 75.05,20.275 75.575,19.75 U11.3@75.575,18.575
RAM_D20: U8.A8 U11.6 | length 41.3
  Top Layer w0.15: U8.A8@69,36 69,26 69.233,25.767 cw(c69.148,25.682) 69.233,25.597 68.884,25.248 ccw(c68.969,25.163) 68.884,25.078 68.927,25.036 ccw(c69.012,25.121) 69.096,25.036 69.964,25.904 cw(c70.049,25.819) 70.134,25.904 70.176,25.861 cw(c70.091,25.776) 70.176,25.692 69.742,25.258 69.309,24.824 ccw(c69.393,24.739) 69.309,24.654 69.351,24.612 ccw(c69.436,24.696) 69.521,24.612 70.388,25.479 cw(c70.473,25.394) 70.558,25.479 70.601,25.437 cw(c70.516,25.352) 70.601,25.267 69.733,24.399 ccw(c69.818,24.315) 69.733,24.23 69.775,24.187 ccw(c69.86,24.272) 69.945,24.187 70.379,24.621 70.813,25.055 cw(c70.898,24.97) 70.982,25.055 71.025,25.013 cw(c70.94,24.928) 71.025,24.843 70.157,23.975 ccw(c70.242,23.89) 70.157,23.805 70.2,23.763 ccw(c70.284,23.848) 70.369,23.763 71.237,24.631 cw(c71.322,24.546) 71.407,24.631 ; 71.048,22.915 71.006,22.957 cw(c71.091,23.042) 71.006,23.126 71.44,23.56 71.873,23.994 ; 71.048,22.914 ccw(c71.133,22.999) 71.218,22.915 72.085,23.782 cw(c72.17,23.697) 72.255,23.782 72.298,23.74 cw(c72.213,23.655) 72.298,23.57 71.949,23.221 ; 71.407,24.631 71.449,24.588 cw(c71.364,24.503) 71.449,24.419 ; 71.449,24.419 71.015,23.985 70.581,23.551 ccw(c70.666,23.466) 70.581,23.381 70.624,23.339 ccw(c70.709,23.424) 70.793,23.339 71.661,24.206 ; 71.661,24.207 cw(c71.746,24.122) 71.831,24.206 71.873,24.164 cw(c71.789,24.079) 71.874,23.994 ; 71.948,23.052 cw(c72.033,23.136) 71.948,23.221 ; 71.949,23.051 72.2,22.8 72.85,22.8 73.65,22 73.65,21.87 ccw(c73.77,21.87) 73.77,21.75 74.18,21.75 cw(c74.18,21.63) 74.3,21.63 74.3,21.57 cw(c74.18,21.57) 74.18,21.45 73.326,21.45 ccw(c73.326,21.33) 73.206,21.33 73.206,21.27 ccw(c73.326,21.27) 73.326,21.15 74.18,21.15 cw(c74.18,21.03) 74.3,21.03 74.3,20.97 cw(c74.18,20.97) 74.18,20.85 73.317,20.85 ccw(c73.317,20.73) 73.197,20.73 73.197,20.67 ccw(c73.317,20.67) 73.317,20.55 74.18,20.55 cw(c74.18,20.43) 74.3,20.43 74.3,20.37 cw(c74.18,20.37) 74.18,20.25 73.77,20.25 ccw(c73.77,20.13) 73.65,20.13 U11.6@73.65,18.35
RAM_D21: U8.C9 U11.7 | length 41.3
  Top Layer w0.15: 67.834,23.458 ccw(c67.919,23.543) 68.004,23.459 68.741,24.196 cw(c68.826,24.111) 68.911,24.196 68.954,24.154 cw(c68.869,24.069) 68.954,23.984 68.216,23.246 ccw(c68.301,23.162) 68.216,23.077 68.258,23.034 ccw(c68.343,23.119) 68.428,23.034 69.166,23.772 cw(c69.251,23.687) 69.335,23.772 69.378,23.729 cw(c69.293,23.645) 69.378,23.56 68.64,22.822 ccw(c68.725,22.737) 68.64,22.653 ; 67.834,23.459 67.792,23.501 cw(c67.877,23.586) 67.792,23.671 68.529,24.408 ccw(c68.444,24.493) 68.529,24.578 68.487,24.62 ccw(c68.402,24.536) 68.317,24.62 68.033,24.336 ; U8.C9@68,38 68.45,37.55 68.45,26.35 67.7,25.6 67.7,25.37 cw(c67.58,25.37) 67.58,25.25 67.178,25.25 ccw(c67.178,25.13) 67.058,25.13 67.058,25.07 ccw(c67.178,25.07) 67.178,24.95 67.58,24.95 cw(c67.58,24.83) 67.7,24.83 67.7,24.5 67.863,24.336 ccw(c67.948,24.421) 68.033,24.336 ; 68.64,22.653 68.683,22.61 ccw(c68.768,22.695) 68.852,22.61 ; 68.852,22.61 69.221,22.979 69.59,23.348 cw(c69.675,23.263) 69.76,23.348 69.802,23.305 cw(c69.717,23.22) 69.802,23.135 69.065,22.398 ccw(c69.149,22.313) 69.064,22.228 ; 69.065,22.228 69.107,22.186 ccw(c69.192,22.271) 69.277,22.186 70.014,22.923 cw(c70.099,22.839) 70.184,22.924 70.226,22.881 ; 70.226,22.881 cw(c70.141,22.796) 70.226,22.711 69.489,21.974 ccw(c69.574,21.889) 69.489,21.804 69.531,21.762 ccw(c69.616,21.846) 69.701,21.761 70.438,22.499 cw(c70.523,22.414) 70.608,22.499 70.651,22.457 ; 70.651,22.457 cw(c70.566,22.372) 70.651,22.287 69.913,21.549 ccw(c69.998,21.465) 69.913,21.38 69.955,21.337 ccw(c70.04,21.422) 70.125,21.337 70.409,21.621 cw(c70.494,21.536) 70.579,21.621 70.729,21.471 71.2,21.471 cw(c71.2,21.387) 71.283,21.387 71.283,21.091 ccw(c71.403,21.091) 71.403,20.971 71.463,20.971 ccw(c71.463,21.091) 71.583,21.091 71.583,21.351 cw(c71.703,21.351) 71.703,21.471 72.033,21.471 72.148,21.356 cw(c72.063,21.271) 72.148,21.186 71.964,21.002 ; 71.964,20.833 cw(c72.049,20.918) 71.964,21.002 ; 71.964,20.833 72.006,20.79 ccw(c72.091,20.875) 72.176,20.79 ; 72.176,20.79 72.713,21.328 cw(c72.798,21.243) 72.883,21.328 72.926,21.285 cw(c72.841,21.2) 72.926,21.116 72.742,20.932 ccw(c72.827,20.847) 72.742,20.762 72.975,20.529 72.975,20.27 cw(c72.855,20.27) 72.855,20.15 72.595,20.15 ccw(c72.595,20.03) 72.475,20.03 72.475,19.97 ccw(c72.595,19.97) 72.595,19.85 72.855,19.85 cw(c72.855,19.73) 72.975,19.73 U11.7@72.975,18.575
RAM_D22: U8.D8 U11.8 | length 44
  Top Layer w0.15: v1@68.5,39.325 cw(c68.5,38.903) 68.799,39.201 cw(c69.097,39.5) v1@68.675,39.5 ; v1(68.5,39.5) U8.D8@69,39 ; v2(71.1,20.4) 71.6,20.4 72.325,19.675 U11.8@72.325,18.575 ; v2@71.224,20.276 cw(c71.522,19.978) 71.522,20.4 cw(c71.522,20.822) v2@71.224,20.524
  Mid-Layer 2 w0.15: v1@68.5,39.325 cw(c68.5,38.903) 68.799,39.201 cw(c69.097,39.5) v1@68.675,39.5 ; v1(68.5,39.5) 69,39 69,37.1 72.35,33.75 72.35,33.2 ccw(c72.575,33.2) 72.575,32.975 72.625,32.975 cw(c72.625,32.75) 72.85,32.75 cw(c72.625,32.75) 72.625,32.525 72.075,32.525 ccw(c72.075,32.3) 71.85,32.3 ccw(c72.075,32.3) 72.075,32.075 72.625,32.075 cw(c72.625,31.85) 72.85,31.85 cw(c72.625,31.85) 72.625,31.625 72.075,31.625 ccw(c72.075,31.4) 71.85,31.4 ccw(c72.075,31.4) 72.075,31.175 72.625,31.175 cw(c72.625,30.95) 72.85,30.95 cw(c72.625,30.95) 72.625,30.725 72.075,30.725 ccw(c72.075,30.5) 71.85,30.5 ccw(c72.075,30.5) 72.075,30.275 72.625,30.275 cw(c72.625,30.05) 72.85,30.05 cw(c72.625,30.05) 72.625,29.825 72.075,29.825 ccw(c72.075,29.6) 71.85,29.6 ccw(c72.075,29.6) 72.075,29.375 72.625,29.375 cw(c72.625,29.15) 72.85,29.15 cw(c72.625,29.15) 72.625,28.925 72.075,28.925 ccw(c72.075,28.7) 71.85,28.7 ccw(c72.075,28.7) 72.075,28.475 72.625,28.475 cw(c72.625,28.25) 72.85,28.25 cw(c72.625,28.25) 72.625,28.025 72.075,28.025 ccw(c72.075,27.8) 71.85,27.8 ccw(c72.075,27.8) 72.075,27.575 72.625,27.575 cw(c72.625,27.35) 72.85,27.35 cw(c72.625,27.35) 72.625,27.125 72.075,27.125 ccw(c72.075,26.9) 71.85,26.9 ccw(c72.075,26.9) 72.075,26.675 72.625,26.675 cw(c72.625,26.45) 72.85,26.45 cw(c72.625,26.45) 72.625,26.225 72.075,26.225 ccw(c72.075,26) 71.85,26 ccw(c72.075,26) 72.075,25.775 72.625,25.775 cw(c72.625,25.55) 72.85,25.55 cw(c72.625,25.55) 72.625,25.325 72.075,25.325 ccw(c72.075,25.1) 71.85,25.1 ccw(c72.075,25.1) 72.075,24.875 72.625,24.875 cw(c72.625,24.65) 72.85,24.65 cw(c72.625,24.65) 72.625,24.425 72.075,24.425 ccw(c72.075,24.2) 71.85,24.2 ccw(c72.075,24.2) 72.075,23.975 72.625,23.975 cw(c72.625,23.75) 72.85,23.75 cw(c72.625,23.75) 72.625,23.525 72.575,23.525 ccw(c72.575,23.3) 72.35,23.3 72.35,21.65 v2(71.1,20.4) ; v2@71.1,20.575 ccw(c71.1,20.997) 71.399,20.699 ccw(c71.697,20.4) v2@71.275,20.4
RAM_D23: U8.H13 U11.9 | length 43.5
  Top Layer w0.15: U8.H13@64.025,43.025 v1(64.55,42.5) ; v1@64.375,42.5 ccw(c63.953,42.5) 64.251,42.799 ccw(c64.55,43.097) v1@64.55,42.675 ; v2@68.45,21.875 cw(c68.45,21.453) 68.749,21.751 cw(c69.047,22.05) v2@68.625,22.05 ; v2(68.45,22.05) 70.6,19.9 71.475,19.9 71.675,19.7 U11.9@71.675,18.575
  Mid-Layer 2 w0.15: v1(64.55,42.5) 65.25,42.5 66.075,41.675 66.075,39.726 66.025,39.676 66.025,37.825 66.1,37.75 66.1,36.75 68.475,34.375 68.475,33.85 ccw(c68.6,33.85) 68.6,33.725 cw(c68.6,33.5) 68.825,33.5 cw(c68.6,33.5) 68.6,33.275 68.35,33.275 ccw(c68.35,33.05) 68.125,33.05 ccw(c68.35,33.05) 68.35,32.825 68.6,32.825 cw(c68.6,32.6) 68.825,32.6 cw(c68.6,32.6) 68.6,32.375 68.35,32.375 ccw(c68.35,32.15) 68.125,32.15 ccw(c68.35,32.15) 68.35,31.925 68.6,31.925 cw(c68.6,31.7) 68.825,31.7 cw(c68.6,31.7) 68.6,31.475 68.35,31.475 ccw(c68.35,31.25) 68.125,31.25 ccw(c68.35,31.25) 68.35,31.025 68.6,31.025 cw(c68.6,30.8) 68.825,30.8 cw(c68.6,30.8) 68.6,30.575 68.35,30.575 ccw(c68.35,30.35) 68.125,30.35 ccw(c68.35,30.35) 68.35,30.125 68.6,30.125 cw(c68.6,29.9) 68.825,29.9 cw(c68.6,29.9) 68.6,29.675 68.35,29.675 ccw(c68.35,29.45) 68.125,29.45 ccw(c68.35,29.45) 68.35,29.225 68.6,29.225 cw(c68.6,29) 68.825,29 cw(c68.6,29) 68.6,28.775 68.35,28.775 ccw(c68.35,28.55) 68.125,28.55 ccw(c68.35,28.55) 68.35,28.325 68.6,28.325 cw(c68.6,28.1) 68.825,28.1 cw(c68.6,28.1) 68.6,27.875 68.35,27.875 ccw(c68.35,27.65) 68.125,27.65 ccw(c68.35,27.65) 68.35,27.425 68.6,27.425 cw(c68.6,27.2) 68.825,27.2 cw(c68.6,27.2) 68.6,26.975 68.35,26.975 ccw(c68.35,26.75) 68.125,26.75 ccw(c68.35,26.75) 68.35,26.525 68.6,26.525 cw(c68.6,26.3) 68.825,26.3 cw(c68.6,26.3) 68.6,26.075 68.35,26.075 ccw(c68.35,25.85) 68.125,25.85 ccw(c68.35,25.85) 68.35,25.625 68.6,25.625 cw(c68.6,25.4) 68.825,25.4 cw(c68.6,25.4) 68.6,25.175 68.35,25.175 ccw(c68.35,24.95) 68.125,24.95 ccw(c68.35,24.95) 68.35,24.725 68.6,24.725 cw(c68.6,24.5) 68.825,24.5 cw(c68.6,24.5) 68.6,24.275 68.35,24.275 ccw(c68.35,24.05) 68.125,24.05 ccw(c68.35,24.05) 68.35,23.825 68.6,23.825 cw(c68.6,23.6) 68.825,23.6 cw(c68.6,23.6) 68.6,23.375 68.35,23.375 ccw(c68.35,23.15) 68.125,23.15 ccw(c68.35,23.15) 68.35,22.925 68.6,22.925 cw(c68.6,22.7) 68.825,22.7 cw(c68.6,22.7) 68.6,22.475 ccw(c68.6,22.35) 68.475,22.35 ; v1@64.674,42.376 cw(c64.972,42.078) 64.972,42.5 cw(c64.972,42.922) v1@64.674,42.624 ; v2@68.383,22.212 ccw(c68.325,22.35) 68.475,22.35 ; v2(68.45,22.05) 68.475,22.075 68.475,22.35 ; v2@68.555,22.19 cw(c68.675,22.35) 68.475,22.35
